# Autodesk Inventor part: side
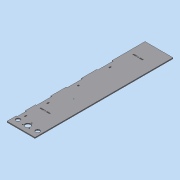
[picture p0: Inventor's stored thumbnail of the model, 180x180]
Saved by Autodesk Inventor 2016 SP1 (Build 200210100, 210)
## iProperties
Created: 2016-06
Part Number: side
Material: Generic
Document SubType Name: Modeling
Designer: Mohamed A.
Density: 1 g/cm^3
Appearance: Default
d0: 85.000 mm
d1: 320.000 mm
d2: 3.000 mm
d3: 0.00 deg
d6: 3.000 mm
d4: 233.000 mm
Author: Mohamed A.
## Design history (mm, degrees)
sketch "Sketch1"
  geometry: L1 (-42.5, 160)-(42.5, 160); L2 (42.5, 160)-(42.5, -160); L3 (42.5, -160)-(-42.5, -160); L4 (-42.5, -160)-(-42.5, 160); L5 (-42.5, 160)-(42.5, -160); L6 (42.5, 160)-(-42.5, -160); 1 further point
  constraints: 12 end point, 2 midpoint, 2 parallel, 1 horizontal, 1 perpendicular
  dimensions: "d0" = 85 distance of L2.end L3.end; "d1" = 320 distance of L1.end L2.end
extrude "Extrusion1" new body sketch "Sketch1" distance "d2" = 3; taper "d3" = 0 deg
sketch "Sketch2"
  geometry: L1 (-26.505, -73)-(-16.505, -73) reference; L2 (-7.505, -76)-(2.495, -76) reference; L3 (42.5, 160)-(-42.5, 160) reference; L4 (-42.5, 113.4)-(-39.5, 113.4); L5 (-39.5, 113.4)-(-39.5, 160); L6 (-42.5, 66.8)-(-39.5, 66.8); L7 (-39.5, 66.8)-(-39.5, 20.2); L8 (-39.5, 20.2)-(-42.5, 20.2); L9 (-39.5, -26.4)-(-42.5, -26.4); L10 (-42.5, -26.4)-(-42.5, -73); L11 (-39.5, 160)-(-42.5, 160); L12 (-42.5, 113.4)-(-42.5, 160); L13 (-42.5, 66.8)-(-42.5, 20.2); L14 (-39.5, -26.4)-(-39.5, -73); L15 (-42.5, -73)-(-39.5, -73); L16 (-42.5, -104)-(-39.5, -104); L17 (-39.5, -104)-(-39.5, -132); L18 (-39.5, -132)-(-42.5, -132); L19 (-42.5, -132)-(-42.5, -104); L20 (-42.5, -160)-(42.5, -160) reference; 1 further point; 1 other entity
  constraints: 32 end point, 6 perpendicular, 5 horizontal, 3 parallel, 2 point on line, 2 vertical, 1 collinear, 2 other
  dimensions: "d4" = 233 distance from line of L3 L1.start (derived); "d6" = 3 distance of L4.start L4.end; "d7" = 46.6 distance between parallel lines of L3 L4 (= 0.2 x d4); "d8" = 3 distance of L6.start L6.end; "d9" = 46.6 distance between parallel lines of L4 L6 (= d7); "d10" = 46.6 distance between parallel lines of L6 L8 (= d7); "d11" = 46.6 distance between parallel lines of L9 L8 (= d10); "d16" = 3 distance of L17.end L18.end; "d17" = 28 distance between parallel lines of L18 L16 (= 0.333333 x d18); "d18" = 84 distance between parallel lines of L20 L2 (derived); "d19" = 28 distance between parallel lines of L16 L2 (= d17); "d20" = 3 distance between parallel lines of L10 L14
extrude "Extrusion2" cut sketch "Sketch2" distance "d12" = 10; taper "d13" = 0 deg
sketch "Sketch3"
  geometry: L1 (-29.5, 142.2)-(-26.5, 142.2); L2 (-26.5, 142.2)-(-26.5, 136.2); L3 (-26.5, 136.2)-(-29.5, 136.2); L4 (-29.5, 136.2)-(-29.5, 142.2); L5 (-29.5, 45.05)-(-26.5, 45.05); L6 (-26.5, 45.05)-(-26.5, 40.5); L7 (-26.5, 40.5)-(-29.5, 40.5); L8 (-29.5, 40.5)-(-29.5, 45.05); L9 (-29.5, -46.7)-(-26.5, -46.7); L10 (-26.5, -46.7)-(-26.5, -52.7); L11 (-26.5, -52.7)-(-29.5, -52.7); L12 (-29.5, -52.7)-(-29.5, -46.7); L13 (-29.5, -115)-(-26.5, -115); L14 (-26.5, -115)-(-26.5, -121); L15 (-26.5, -121)-(-29.5, -121); L16 (-29.5, -121)-(-29.5, -115); L17 (-10.455, 130)-(-13.555, 130) reference; L18 (-10.455, 130)-(-10.455, 127) reference; L19 (-13.555, 127)-(-10.455, 127) reference; L20 (-13.555, 130)-(-13.555, 127) reference; L21 (-10.455, -73)-(-13.555, -73) reference; L22 (-10.455, -73)-(-10.455, -76) reference; L23 (-13.555, -76)-(-10.455, -76) reference; L24 (-13.555, -73)-(-13.555, -76) reference; L25 (-16.505, 130)-(-16.505, 127) reference; L26 (-16.505, 127)-(-26.505, 127) reference; L27 (-26.505, 127)-(-26.505, 130) reference; L28 (-26.505, 130)-(-16.505, 130) reference; L29 (-7.505, 127)-(-7.505, 130) reference; L30 (-7.505, 130)-(2.495, 130) reference; L31 (2.495, 130)-(2.495, 127) reference; L32 (2.495, 127)-(-7.505, 127) reference; L33 (2.495, -73)-(2.495, -76) reference; L34 (2.495, -76)-(-7.505, -76) reference; L35 (-7.505, -76)-(-7.505, -73) reference; L36 (-7.505, -73)-(2.495, -73) reference; L37 (-26.505, -76)-(-26.505, -73) reference; L38 (-26.505, -73)-(-16.505, -73) reference; L39 (-16.505, -73)-(-16.505, -76) reference; L40 (-16.505, -76)-(-26.505, -76) reference; L41 (-21, -118)-(-21, -160) reference; L42 (21, -160)-(21, -118) reference; L43 (-39.5, 160)-(-39.5, 113.4) reference; L44 (-39.5, 160)-(42.5, 160) reference; C1 r 1.4 at (-12.005, 128.5); C2 r 1.4 at (-12.005, -74.5); C3 r 6.3 at (-29.7, -139); C4 r 6.3 at (29.7, -139); C5 r 8.05 at (0, -139) reference; C6 r 8.05 at (0, -139) reference; C7 r 8.5 at (0, -139); C8 r 2 at (0, -127.543) reference; C9 r 2 at (9.922, -144.728) reference; C10 r 2 at (-9.922, -144.728) reference; C11 r 1.4 at (0, -127.543); C12 r 1.4 at (9.922, -144.728); C13 r 1.4 at (-9.922, -144.728); 9 further points
  constraints: 64 end point, 12 horizontal, 8 centre point, 8 parallel, 8 vertical, 4 perpendicular, 3 coincident, 32 other
  dimensions: "d22" = 2.8 diameter of C1; "d23" = 2.8 diameter of C2; "d24" = 12.6 diameter of C3; "d25" = 8.7 distance from line of C3.centre L41; "d26" = 42 distance of L41.start L41.end (derived); "d27" = 21 vertical distance of C3.centre L41.start (= 0.5 x d26); "d28" = 12.6 diameter of C4; "d29" = 21 vertical distance of C4.centre L42.end; "d30" = 8.7 distance from line of L42 C4.centre (= d25); "d32" = 2.8 diameter of C11; "d33" = 2.8 diameter of C12; "d34" = 2.8 diameter of C13; "d35" = 17 diameter of C7; "d38" = 12.99471 distance between parallel lines of L43 L27 (derived); "d39" = 10 distance of L27.end L25.start (derived); "d40" = 9 distance between parallel lines of L25 L29 (derived); "d41" = 10 distance between parallel lines of L29 L31 (derived); "d42" = 30 distance between parallel lines of L44 L28 (derived)
extrude "Extrusion3" cut sketch "Sketch3" distance "d14" = 10; taper "d15" = 0 deg
sketch "Sketch4"
  geometry: 1 further point
sketch "Sketch5"
  geometry: L1 (-82, 3)-(-82, 0) reference; L2 (0, 0)-(-82, 0) reference; L3 (0, 3)-(0, 0) reference; L4 (-82, 3)-(0, 3) reference; L5 (-82, 0)-(-85, 0) reference; L6 (-82, 3)-(-85, 3); L7 (-85, 3)-(-85, 0); L8 (-85, 0)-(-82, 0); L9 (-82, 0)-(-82, 3); 1 further point
  constraints: 8 end point, 2 parallel, 1 horizontal, 1 perpendicular
extrude "Extrusion4" join sketch "Sketch5" distance "d36" = 100; taper "d37" = 0 deg
sketch "Sketch6"
  geometry: L1 (-26.505, 210)-(-16.505, 210); L2 (-16.505, 210)-(-16.505, 207); L3 (-16.505, 207)-(-26.505, 207); L4 (-26.505, 207)-(-26.505, 210); L5 (-7.505, 210)-(2.495, 210); L6 (2.495, 210)-(2.495, 207); L7 (2.495, 207)-(-7.505, 207); L8 (-7.505, 207)-(-7.505, 210); L9 (-42.5, 160)-(-42.5, 260) reference; L10 (-42.5, 260)-(42.5, 260) reference; L11 (-7.505, 210)-(-16.505, 207); L12 (-7.505, 207)-(-16.505, 210); C1 r 1.4 at (-12.005, 208.5); 1 further point
  constraints: 20 end point, 4 parallel, 2 horizontal, 2 perpendicular, 1 centre point, 1 collinear, 1 midpoint
  dimensions: "d43" = 10 distance of L2.end L3.end; "d44" = 3 distance of L1.end L2.end; "d45" = 10 distance of L6.end L7.end; "d46" = 3 distance of L5.end L6.end; "d47" = 9 distance between parallel lines of L2 L8; "d48" = 15.995 distance between parallel lines of L9 L4; "d49" = 50 distance between parallel lines of L10 L1; "d50" = 2.8 diameter of C1
extrude "Extrusion5" cut sketch "Sketch6" distance "d51" = 100; taper "d52" = 0 deg
body "Solid1"
node "Reference3"
node "Reference4"
node "Reference5"
node "Reference6"
node "Reference7"
node "Reference8"
node "Reference9"
node "Reference10"
node "Reference11"
node "Reference12"
node "Reference13"
node "Projected Loop1"
